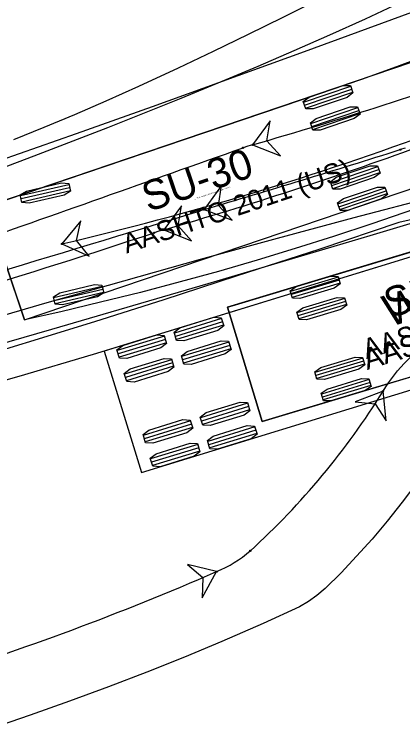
# Model space of a CAD drawing. Extents: x 2096670 to 2098561, y 684033 to 689893.
# Drawn here: x 2097611.95 to 2097637.92, y 685827.59 to 685875.39 of the extents above; entities that cross this region are included whole.
import ezdxf

# ---------------------------------------------------------------- set-up
doc = ezdxf.new("R2010")
doc.units = 0
doc.layers.add('Old_Level_63', color=7, linetype='Continuous')

msp = doc.modelspace()

# ---------------------------------------------------------------- linework, layer by layer
at = {"layer": 'Old_Level_63'}
for p, q in [((2097638.478, 685872.163), (2097610.065, 685862.533)), ((2097631.284, 685869.505), (2097634.441, 685870.575)), ((2097631.351, 685869.307), (2097634.507, 685870.377)), ((2097631.417, 685869.11), (2097634.574, 685870.18)), ((2097631.765, 685868.084), (2097634.922, 685869.154)), ((2097631.832, 685867.887), (2097634.989, 685868.957)), ((2097631.899, 685867.689), (2097635.056, 685868.759)), ((2097663.828, 685866.968), (2097617.949, 685852.856)), ((2097633.103, 685864.138), (2097636.26, 685865.208)), ((2097633.17, 685863.941), (2097636.327, 685865.011)), ((2097612.634, 685854.956), (2097641.046, 685864.586)), ((2097633.237, 685863.743), (2097636.393, 685864.813)), ((2097612.356, 685863.259), (2097615.603, 685864.013)), ((2097654.93, 685864.455), (2097626.208, 685855.794)), ((2097612.404, 685863.056), (2097615.651, 685863.81)), ((2097612.451, 685862.853), (2097615.698, 685863.607)), ((2097633.584, 685862.717), (2097636.741, 685863.787)), ((2097633.651, 685862.52), (2097636.808, 685863.59)), ((2097633.718, 685862.323), (2097636.875, 685863.393)), ((2097610.065, 685862.533), (2097612.634, 685854.956)), ((2097620.448, 685844.731), (2097666.327, 685858.844)), ((2097633.608, 685857.808), (2097630.417, 685856.846)), ((2097633.668, 685857.609), (2097630.477, 685856.646)), ((2097633.728, 685857.409), (2097630.537, 685856.447)), ((2097614.58, 685856.445), (2097617.824, 685857.208)), ((2097614.627, 685856.242), (2097617.872, 685857.005)), ((2097614.675, 685856.039), (2097617.92, 685856.803)), ((2097628.517, 685848.135), (2097657.24, 685856.796)), ((2097634.041, 685856.372), (2097630.85, 685855.41)), ((2097634.101, 685856.173), (2097630.91, 685855.21)), ((2097634.162, 685855.973), (2097630.97, 685855.011)), ((2097626.208, 685855.794), (2097628.517, 685848.135)), ((2097612.634, 685854.956), (2097612.634, 685854.956)), ((2097625.807, 685855.033), (2097622.652, 685854.063)), ((2097625.874, 685854.814), (2097622.72, 685853.844)), ((2097625.941, 685854.595), (2097622.787, 685853.625)), ((2097621.983, 685853.857), (2097618.829, 685852.887)), ((2097622.051, 685853.638), (2097618.897, 685852.668)), ((2097622.118, 685853.419), (2097618.964, 685852.449)), ((2097626.292, 685853.456), (2097623.138, 685852.486)), ((2097626.359, 685853.237), (2097623.205, 685852.267)), ((2097626.426, 685853.018), (2097623.272, 685852.048)), ((2097617.949, 685852.856), (2097620.448, 685844.731)), ((2097622.468, 685852.28), (2097619.314, 685851.31)), ((2097622.536, 685852.061), (2097619.382, 685851.091)), ((2097635.244, 685852.383), (2097632.053, 685851.421)), ((2097635.304, 685852.183), (2097632.113, 685851.221)), ((2097622.603, 685851.842), (2097619.449, 685850.872)), ((2097635.364, 685851.984), (2097632.173, 685851.022)), ((2097635.677, 685850.947), (2097632.486, 685849.984)), ((2097635.737, 685850.747), (2097632.546, 685849.785)), ((2097635.798, 685850.548), (2097632.606, 685849.586)), ((2097627.551, 685849.362), (2097624.397, 685848.392)), ((2097627.618, 685849.143), (2097624.464, 685848.173)), ((2097627.686, 685848.924), (2097624.532, 685847.954)), ((2097623.728, 685848.186), (2097620.574, 685847.216)), ((2097623.795, 685847.967), (2097620.641, 685846.997)), ((2097628.036, 685847.785), (2097624.882, 685846.815)), ((2097623.863, 685847.748), (2097620.708, 685846.777)), ((2097628.104, 685847.566), (2097624.949, 685846.595)), ((2097628.171, 685847.347), (2097625.017, 685846.376)), ((2097624.213, 685846.609), (2097621.059, 685845.638)), ((2097624.28, 685846.39), (2097621.126, 685845.419)), ((2097624.348, 685846.171), (2097621.194, 685845.2))]:
    msp.add_line(p, q, dxfattribs=at)
for points in [[(2097611.027, 685865.635), (2097616.113, 685867.407), (2097621.195, 685869.216), (2097631.356, 685872.914), (2097644.361, 685877.697), (2097646.901, 685878.659), (2097649.442, 685879.648), (2097654.215, 685881.571), (2097654.52, 685881.765), (2097655.712, 685882.687), (2097656.916, 685883.581), (2097658.129, 685884.446), (2097659.355, 685885.285), (2097660.596, 685886.098), (2097661.228, 685886.456), (2097663.81, 685887.688), (2097665.447, 685888.429), (2097668.097, 685889.57), (2097670.755, 685890.808)], [(2097626.522, 685855.889), (2097654.577, 685864.349), (2097659.655, 685865.807), (2097666.553, 685867.754), (2097669.015, 685868.577), (2097671.467, 685869.43), (2097673.908, 685870.315), (2097676.337, 685871.231), (2097678.755, 685872.178), (2097681.16, 685873.156), (2097683.553, 685874.164), (2097685.932, 685875.203), (2097688.298, 685876.272), (2097690.65, 685877.371), (2097692.988, 685878.5), (2097695.311, 685879.658), (2097697.622, 685880.848), (2097699.9, 685882.058)], [(2097608.327, 685864.059), (2097613.286, 685865.914), (2097618.215, 685867.819), (2097623.111, 685869.781), (2097625.845, 685870.909), (2097628.261, 685871.928), (2097630.666, 685872.965), (2097633.057, 685874.022), (2097635.429, 685875.097), (2097638.075, 685876.331)], [(2097611.915, 685867.019), (2097613.947, 685867.835), (2097616.001, 685868.698), (2097618.083, 685869.605), (2097620.277, 685870.59), (2097622.919, 685871.807), (2097625.273, 685872.92), (2097627.612, 685874.053), (2097629.935, 685875.208), (2097632.237, 685876.384)], [(2097638.715, 685862.356), (2097635.843, 685861.37), (2097633.286, 685860.522), (2097630.732, 685859.711), (2097628.178, 685858.935), (2097625.614, 685858.192), (2097623.035, 685857.48), (2097620.378, 685856.782), (2097617.717, 685856.12), (2097615.053, 685855.493), (2097612.634, 685854.956), (2097610.065, 685862.533), (2097629.945, 685869.271), (2097635.248, 685871.084), (2097637.708, 685871.968), (2097640.151, 685872.882)], [(2097671.399, 685871.229), (2097669.99, 685870.706), (2097668.573, 685870.233), (2097667.142, 685869.806), (2097665.684, 685869.419), (2097662.839, 685868.59), (2097661.407, 685868.217), (2097659.964, 685867.879), (2097657.78, 685867.441), (2097657.427, 685867.351), (2097652.017, 685865.598), (2097646.662, 685863.902), (2097641.004, 685862.157), (2097635.721, 685860.567), (2097624.882, 685857.361), (2097614.448, 685854.31), (2097603.853, 685851.239)], [(2097609.816, 685850.484), (2097612.285, 685851.185), (2097617.256, 685852.655), (2097642.794, 685860.498), (2097644.054, 685860.899), (2097646.457, 685862.084), (2097648.874, 685863.222), (2097651.305, 685864.315), (2097653.75, 685865.362), (2097656.192, 685866.356), (2097657.414, 685866.834), (2097659.884, 685867.703), (2097662.369, 685868.521), (2097664.87, 685869.29), (2097667.389, 685870.01), (2097669.951, 685870.687), (2097672.53, 685871.313)], [(2097699.852, 685871.449), (2097697.423, 685870.233), (2097694.979, 685869.049), (2097692.521, 685867.895), (2097690.047, 685866.773), (2097687.56, 685865.683), (2097685.058, 685864.625), (2097684.428, 685864.373), (2097666.174, 685859.152), (2097663.602, 685858.37), (2097661.028, 685857.622), (2097658.459, 685865.206), (2097660.383, 685857.44), (2097655.238, 685856.05), (2097645.059, 685853.086), (2097634.895, 685850.058), (2097628.517, 685848.135), (2097626.208, 685855.794), (2097626.522, 685855.889), (2097626.522, 685855.889)], [(2097670.627, 685870.948), (2097669.186, 685870.411), (2097667.723, 685869.921), (2097666.24, 685869.479), (2097664.747, 685869.087), (2097663.23, 685868.743), (2097661.682, 685868.446), (2097660.117, 685868.2), (2097659.353, 685868.056), (2097658.622, 685867.869), (2097657.921, 685867.638), (2097656.227, 685866.983), (2097654.863, 685866.479), (2097649.41, 685864.6), (2097646.672, 685863.74), (2097643.914, 685862.955), (2097641.139, 685862.245), (2097637.653, 685861.451), (2097632.385, 685859.681), (2097626.785, 685857.876), (2097621.955, 685856.294), (2097617.307, 685854.818), (2097607.866, 685851.921)], [(2097671.007, 685870.02), (2097668.46, 685869.577), (2097665.602, 685869.047), (2097663.062, 685868.548), (2097660.515, 685868.025), (2097655.42, 685866.916), (2097650.32, 685865.732), (2097645.215, 685864.488), (2097640.109, 685863.193), (2097634.659, 685861.768), (2097629.517, 685860.389), (2097624.381, 685858.979), (2097619.249, 685857.543), (2097614.121, 685856.081), (2097608.998, 685854.597)], [(2097627.879, 685866.658), (2097629.74, 685865.926), (2097628.84, 685866.934), (2097629.068, 685868.266), (2097627.879, 685866.658)], [(2097627.879, 685866.658), (2097627.559, 685866.567), (2097627.242, 685866.463)], [(2097638.076, 685866.438), (2097637.759, 685866.335)], [(2097624.638, 685862.323), (2097626.506, 685861.608), (2097625.597, 685862.608), (2097625.812, 685863.942), (2097624.638, 685862.323)], [(2097621.942, 685860.97), (2097623.804, 685860.241), (2097622.903, 685861.248), (2097623.129, 685862.58), (2097621.942, 685860.97)], [(2097624.638, 685862.323), (2097624.319, 685862.228)], [(2097615.138, 685860.028), (2097616.96, 685859.204), (2097616.112, 685860.256), (2097616.406, 685861.575), (2097615.138, 685860.028)], [(2097621.942, 685860.97), (2097621.622, 685860.878), (2097621.305, 685860.774)], [(2097636.607, 685850.172), (2097636.782, 685850.456), (2097636.965, 685850.734), (2097637.158, 685851.006), (2097637.359, 685851.272), (2097637.569, 685851.531), (2097637.788, 685851.783), (2097638.015, 685852.027), (2097638.25, 685852.263), (2097638.494, 685852.49), (2097638.745, 685852.709), (2097639.005, 685852.918), (2097639.272, 685853.117), (2097639.547, 685853.306), (2097639.829, 685853.484), (2097640.118, 685853.65)], [(2097636.607, 685850.172), (2097634.736, 685849.465), (2097636.08, 685849.322), (2097636.806, 685848.182), (2097636.607, 685850.172)], [(2097638.859, 685844.05), (2097637.879, 685842.739), (2097636.881, 685841.483), (2097635.868, 685840.28), (2097634.839, 685839.126), (2097633.796, 685838.02), (2097632.736, 685836.962), (2097632.187, 685836.496), (2097631.618, 685836.093), (2097631.029, 685835.749), (2097628.589, 685834.63), (2097625.819, 685833.424), (2097623.327, 685832.381), (2097620.802, 685831.368), (2097618.241, 685830.381), (2097615.644, 685829.424), (2097613.012, 685828.496), (2097610.349, 685827.59)], [(2097625.475, 685838.098), (2097625.78, 685838.232), (2097626.08, 685838.377), (2097626.374, 685838.534), (2097626.661, 685838.704), (2097626.941, 685838.885), (2097627.213, 685839.077), (2097627.477, 685839.281), (2097627.731, 685839.496)], [(2097625.475, 685838.098), (2097623.534, 685838.58), (2097624.558, 685837.699), (2097624.507, 685836.348), (2097625.475, 685838.098)]]:
    msp.add_lwpolyline(points, dxfattribs=at)
for points in [[(2097631.434, 685869.061), (2097631.267, 685869.554), (2097631.659, 685869.852), (2097633.932, 685870.622), (2097634.424, 685870.624), (2097634.591, 685870.131), (2097634.199, 685869.833), (2097631.926, 685869.062)], [(2097631.916, 685867.64), (2097631.749, 685868.133), (2097632.14, 685868.431), (2097634.413, 685869.202), (2097634.906, 685869.203), (2097635.072, 685868.711), (2097634.681, 685868.412), (2097632.408, 685867.642)], [(2097627.879, 685866.658), (2097629.74, 685865.926), (2097628.84, 685866.934), (2097629.068, 685868.266)], [(2097633.253, 685863.694), (2097633.086, 685864.187), (2097633.478, 685864.485), (2097635.751, 685865.255), (2097636.243, 685865.257), (2097636.41, 685864.764), (2097636.018, 685864.466), (2097633.745, 685863.696)], [(2097612.462, 685862.803), (2097612.345, 685863.31), (2097612.764, 685863.568), (2097615.102, 685864.111), (2097615.592, 685864.064), (2097615.709, 685863.557), (2097615.29, 685863.299), (2097612.952, 685862.756)], [(2097624.638, 685862.323), (2097626.506, 685861.608), (2097625.597, 685862.608), (2097625.812, 685863.942)], [(2097633.735, 685862.274), (2097633.568, 685862.766), (2097633.959, 685863.064), (2097636.232, 685863.835), (2097636.725, 685863.836), (2097636.892, 685863.344), (2097636.5, 685863.046), (2097634.227, 685862.275)], [(2097621.942, 685860.97), (2097623.804, 685860.241), (2097622.903, 685861.248), (2097623.129, 685862.58)], [(2097615.138, 685860.028), (2097616.96, 685859.204), (2097616.112, 685860.256), (2097616.406, 685861.575)], [(2097633.593, 685857.858), (2097633.743, 685857.36), (2097633.342, 685857.075), (2097631.044, 685856.382), (2097630.552, 685856.398), (2097630.402, 685856.895), (2097630.803, 685857.18), (2097633.101, 685857.873)], [(2097614.687, 685855.989), (2097614.568, 685856.495), (2097614.986, 685856.754), (2097617.322, 685857.304), (2097617.813, 685857.259), (2097617.932, 685856.752), (2097617.513, 685856.493), (2097615.177, 685855.943)], [(2097634.026, 685856.422), (2097634.176, 685855.924), (2097633.775, 685855.639), (2097631.477, 685854.946), (2097630.985, 685854.961), (2097630.835, 685855.459), (2097631.237, 685855.744), (2097633.534, 685856.437)], [(2097625.79, 685855.087), (2097625.958, 685854.541), (2097625.567, 685854.24), (2097623.296, 685853.541), (2097622.804, 685853.57), (2097622.636, 685854.117), (2097623.027, 685854.418), (2097625.298, 685855.116)], [(2097621.967, 685853.911), (2097622.135, 685853.364), (2097621.744, 685853.064), (2097619.473, 685852.365), (2097618.981, 685852.394), (2097618.813, 685852.941), (2097619.203, 685853.242), (2097621.474, 685853.94)], [(2097626.275, 685853.51), (2097626.443, 685852.963), (2097626.052, 685852.663), (2097623.781, 685851.964), (2097623.289, 685851.993), (2097623.121, 685852.54), (2097623.512, 685852.84), (2097625.783, 685853.539)], [(2097622.452, 685852.334), (2097622.62, 685851.787), (2097622.229, 685851.487), (2097619.958, 685850.788), (2097619.466, 685850.817), (2097619.298, 685851.364), (2097619.689, 685851.664), (2097621.96, 685852.363)], [(2097635.229, 685852.432), (2097635.379, 685851.935), (2097634.978, 685851.65), (2097632.68, 685850.957), (2097632.188, 685850.972), (2097632.038, 685851.47), (2097632.439, 685851.755), (2097634.737, 685852.448)], [(2097635.662, 685850.996), (2097635.812, 685850.498), (2097635.411, 685850.214), (2097633.113, 685849.521), (2097632.621, 685849.536), (2097632.471, 685850.034), (2097632.872, 685850.319), (2097635.17, 685851.012)], [(2097636.607, 685850.172), (2097634.736, 685849.465), (2097636.08, 685849.322), (2097636.806, 685848.182)], [(2097627.534, 685849.416), (2097627.702, 685848.869), (2097627.312, 685848.569), (2097625.041, 685847.87), (2097624.548, 685847.899), (2097624.38, 685848.446), (2097624.771, 685848.746), (2097627.042, 685849.445)], [(2097623.711, 685848.24), (2097623.879, 685847.693), (2097623.488, 685847.393), (2097621.217, 685846.694), (2097620.725, 685846.723), (2097620.557, 685847.27), (2097620.948, 685847.57), (2097623.219, 685848.269)], [(2097628.019, 685847.839), (2097628.188, 685847.292), (2097627.797, 685846.992), (2097625.526, 685846.293), (2097625.033, 685846.322), (2097624.865, 685846.869), (2097625.256, 685847.169), (2097627.527, 685847.868)], [(2097624.196, 685846.663), (2097624.364, 685846.116), (2097623.973, 685845.816), (2097621.702, 685845.117), (2097621.21, 685845.146), (2097621.042, 685845.693), (2097621.433, 685845.993), (2097623.704, 685846.692)], [(2097625.475, 685838.098), (2097623.534, 685838.58), (2097624.558, 685837.699), (2097624.507, 685836.348)]]:
    msp.add_lwpolyline(points, close=True, dxfattribs=at)
for centre in [(2097627.242, 685866.463), (2097627.242, 685866.463), (2097627.879, 685866.658), (2097627.879, 685866.658), (2097637.759, 685866.335), (2097637.759, 685866.335), (2097624.319, 685862.228), (2097624.319, 685862.228), (2097624.638, 685862.323), (2097624.638, 685862.323), (2097621.305, 685860.774), (2097621.305, 685860.774), (2097621.942, 685860.97), (2097621.942, 685860.97), (2097615.138, 685860.028), (2097636.607, 685850.172), (2097636.607, 685850.172), (2097627.731, 685839.496), (2097627.731, 685839.496), (2097625.475, 685838.098), (2097625.475, 685838.098)]:
    msp.add_circle(centre, 0.0417, dxfattribs=at)
for centre, radius, start, end in [((2097547.762, 686145.929), 290.536, 286.00706, 289.63667), ((2097567.896, 686062.099), 207.519, 283.1587, 290.4346), ((2095835.659, 690904.556), 5347.162, 289.361063, 289.575757), ((2097549.186, 686112.867), 262.193, 286.1104, 290.02897), ((2097364.532, 686736.325), 911.886, 286.573198, 287.435288), ((2096875.403, 688302.062), 2552.189, 286.381892, 287.064048), ((2097445.829, 686391.634), 559.111, 285.52517, 288.29132), ((2097594.031, 685876.539), 50.079, 312.2951, 328.2306), ((2097550.523, 686009.982), 187.514, 287.17608, 293.56009)]:
    msp.add_arc(centre, radius, start, end, dxfattribs=at)

# ---------------------------------------------------------------- texts
for s, height, rotation, p in [('SU-30', 2, 18.7243, (2097620.904, 685862.152)), ('AASHTO 2011 (US)', 1.33333, 18.7243, (2097619.458, 685859.374)), ('(c) 2023 Transoft Solutions, Inc. All rights reserved.', 0.08, 18.7243, (2097624.017, 685862.996)), ('WB-62', 2.125, 17.0979, (2097637.011, 685854.45)), ('SU-30', 2, 16.7802, (2097637.027, 685855.046)), ('AASHTO 2011 (US)', 1.33333, 16.7802, (2097635.487, 685852.319)), ('AASHTO 2011 (US)', 1.41667, 17.0979, (2097635.535, 685851.588))]:
    msp.add_text(s, height=height, rotation=rotation, dxfattribs=at).set_placement(p)

doc.saveas('drawing.dxf')
